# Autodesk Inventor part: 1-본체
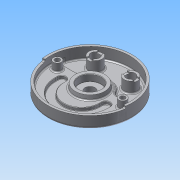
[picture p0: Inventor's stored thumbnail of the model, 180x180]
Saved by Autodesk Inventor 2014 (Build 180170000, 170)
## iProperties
Created: 2015-06
Part Number: 1-본체
Material: 알루미늄 6061
Document SubType Name: Modeling
Designer: Administrator
Density: 2.71 g/cm^3
Appearance: 알루미늄 - 평지
Mass: 1077.33 g
Surface Area: 1041.67 cm^2
Volume: 397.54 cm^3
Author: Administrator
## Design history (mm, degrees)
sketch "스케치1"
  geometry: C1 r 95 at (0, 0); 1 further point
  constraints: 1 centre point, 1 coincident
  dimensions: "d0" = 190 diameter of C1
extrude "돌출1" new body sketch "스케치1" distance "d1" = 32; taper "d2" = 0 deg
sketch "스케치2"
  geometry: C1 r 95 at (0, 0) reference; C2 r 90 at (0, 0)
  constraints: 1 centre point, 1 coincident
  dimensions: "d3" = 180 diameter of C2
extrude "돌출2" cut sketch "스케치2" distance "d4" = 18; taper "d5" = 0 deg
sketch "스케치3"
  geometry: L1 (-88.566, 16)-(88.566, 16); A1 r 90 centre (0, 0) between (-88.566, 16) and (88.566, 16) reference; A2 r 90 centre (0, 0) between (88.566, 16) and (-88.566, 16); A3 r 42 centre (0, 0) between (38.833, 16) and (-38.833, 16)
  constraints: 6 point on circle, 2 centre point, 2 end point, 2 point on line, 1 coincident, 1 concentric, 1 horizontal
  dimensions: "d6" = 16 distance from line of L1 A1.centre; "d7" = 84 diameter of A3
extrude "돌출3" cut sketch "스케치3" distance "d8" = 7; taper "d9" = 0 deg
sketch "스케치4"
  geometry: C1 r 35 at (0, 0); A1 r 42 centre (0, 0) between (38.833, 16) and (-38.833, 16) reference
  constraints: 1 centre point, 1 coincident
  dimensions: "d10" = 70 diameter of C1
extrude "돌출4" join sketch "스케치4" distance "d11" = 10; taper "d12" = -10 deg
sketch "스케치5"
  geometry: L1 (88.566, 16)-(38.833, 16) reference; L2 (-87.972, -19)-(87.972, -19); L3 (0, 0)-(0, -90); L4 (-88.904, -14)-(88.904, -14); L5 (-59, -19)-(-59, -14); L6 (-41, -19)-(-41, -14); L7 (41, -19)-(41, -14); L8 (59, -19)-(59, -14); C1 r 35 at (0, 0) reference; A1 r 90 centre (0, 0) between (-88.566, 16) and (88.566, 16) reference; A2 r 42 centre (0, 0) between (38.833, 16) and (-38.833, 16) reference; A3 r 41 centre (0, -19) between (-41, -19) and (41, -19); A4 r 59 centre (0, -19) between (-59, -19) and (59, -19); A5 r 9 centre (-50, -14) between (-41, -14) and (-59, -14); A6 r 9 centre (50, -14) between (59, -14) and (41, -14)
  constraints: 14 end point, 13 point on circle, 9 point on line, 8 tangent, 4 centre point, 4 perpendicular, 3 parallel, 1 coincident, 1 midpoint
  dimensions: "d13" = 19 distance from line of L2 C1.centre; "d16" = 5 distance between parallel lines of L4 L2; "d17" = 59 radius of A4; "d18" = 41 radius of A3
extrude "돌출5" cut sketch "스케치5" distance "d19" = 7; taper "d20" = 0 deg
sketch "스케치7"
  geometry: L1 (-95, 0)-(95, 0); L2 (-89.124, -12.526)-(-94.075, -13.221); L3 (89.124, -12.526)-(94.075, -13.221); C1 r 95 at (0, 0) reference; A1 r 90 centre (0, 0) between (-89.124, -12.526) and (89.124, -12.526); A2 r 95 centre (0, 0) between (-94.075, -13.221) and (94.075, -13.221); 2 further points
  constraints: 6 end point, 4 point on circle, 2 centre point, 2 coincident, 1 horizontal, 2 other
  dimensions: "d28" = 190 distance of L1.start L1.end; "d29" = 8 deg angle of L2 L1; "d30" = 8 deg angle of L3 L1; "d31" = 95 radius of A2; "d32" = 0 distance from line of point (0, 0) L3; "d33" = 0 distance from line of point (0, 0) L1; "d34" = 0 distance from line of point (0, 0) L2; "d35" = 13.22144 distance from line of L1.end L3
extrude "돌출6" cut sketch "스케치7" distance "d36" = 5; taper "d37" = 0 deg
sketch "스케치8"
  geometry: C1 r 95 at (0, 0) reference; C2 r 15 at (40, 52); C3 r 15 at (-40, 52)
  constraints: 2 centre point, 1 horizontal alignment
  dimensions: "d43" = 30 diameter of C3; "d44" = 30 diameter of C2; "d45" = 80 distance of C3.centre C2.centre; "d46" = 40 horizontal distance of C1.centre C2.centre; "d47" = 52 vertical distance of C1.centre C2.centre
extrude "돌출7" join sketch "스케치8" stored distance "d48" = 7; taper "d49" = 0 deg
sketch "스케치9"
  geometry: C1 r 15 at (0, 0) reference; C2 r 15 at (80, 0) reference; 3 further points
  constraints: 2 coincident
hole "구멍1" sketch "스케치9" at (0, 0), (80, 0) diameter "d50" = 20; stored, may be unused: countersink angle "d54" = 90 deg, drill point angle "d56" = 118 deg; dims "d51" = 6, "d52" = 4, "d53" = 2, "d55" = 8
sketch "스케치10"
  geometry: L1 (6, -19.376)-(-6, -19.376); L2 (-6, -19.376)-(-6, 19.376); L3 (-6, 19.376)-(6, 19.376); L4 (6, 19.376)-(6, -19.376); L5 (6, -19.376)-(-6, 19.376); L6 (-6, -19.376)-(6, 19.376); L7 (59.502, 6)-(100.498, 6); L8 (100.498, 6)-(100.498, -6); L9 (100.498, -6)-(59.502, -6); L10 (59.502, -6)-(59.502, 6); L11 (59.502, 6)-(100.498, -6); L12 (100.498, 6)-(59.502, -6); C1 r 15 at (0, 0) reference; C2 r 10 at (80, 0) reference; C3 r 15 at (80, 0) reference; 3 further points
  constraints: 24 end point, 5 midpoint, 4 parallel, 2 horizontal, 2 perpendicular, 1 coincident
  dimensions: "d57" = 12 distance of L2.end L3.end; "d58" = 12 distance of L9.end L7.start; "d59" = 38.75256 distance of L3.end L1.start; "d60" = 40.99632 distance of L8.end L9.end
extrude "돌출8" cut sketch "스케치10" distance "d61" = 3; taper "d62" = 0 deg
sketch "스케치13"
  geometry: C1 r 95 at (0, 0) reference; C2 r 26 at (0, 0)
  constraints: 1 centre point, 1 coincident
  dimensions: "d71" = 52 diameter of C2
extrude "돌출9" join sketch "스케치13" distance "d72" = 12; taper "d73" = -15 deg
sketch "스케치14"
  geometry: C1 r 33.237 at (0, 0) reference; 1 further point
  constraints: 1 coincident
hole "구멍3" sketch "스케치14" at (0, 0) diameter "d74" = 23; stored, may be unused: countersink angle "d78" = 90 deg, drill point angle "d80" = 118 deg; dims "d75" = 6, "d76" = 50, "d77" = 15, "d79" = 8
sketch "스케치16"
  geometry: L1 (88.566, 16)-(38.833, 16) reference; L2 (-90, 0)-(90, 0); C1 r 9 at (-74, 0); C2 r 9 at (74, 0); A1 r 90 centre (0, 0) between (-88.566, 16) and (88.566, 16) reference; A2 r 42 centre (0, 0) between (38.833, 16) and (-38.833, 16) reference; A3 r 74 centre (0, 0) between (-74, 0) and (74, 0)
  constraints: 4 point on circle, 3 centre point, 2 end point, 2 point on line, 1 coincident, 1 parallel
  dimensions: "d83" = 180 distance of L2.start L2.end; "d84" = 148 diameter of A3; "d85" = 18 diameter of C2; "d86" = 18 diameter of C1
extrude "돌출10" join sketch "스케치16" stored distance "d87" = 12; taper "d88" = 0 deg
sketch "스케치17"
  geometry: C1 r 9 at (-74, 0) reference; C2 r 9 at (74, 0) reference; 2 further points
  constraints: 2 coincident
hole "구멍4" sketch "스케치17" at (-74, 0), (74, 0) diameter "d89" = 11; stored, may be unused: countersink angle "d93" = 90 deg, drill point angle "d95" = 118 deg; dims "d90" = 6, "d91" = 18, "d92" = 11, "d94" = 8
fillet "모깎기1" dims "d96" = 10
fillet "모깎기2" dims "d97" = 3
fillet "모깎기3" dims "d98" = 3
fillet "모깎기4" dims "d99" = 3
fillet "모깎기5" dims "d100" = 3
fillet "모깎기6" dims "d101" = 3
chamfer "모따기1" distance "d102" = 1; stored, may be unused: second distance "d103" = 2, angle "d104" = 45 deg
fillet "모깎기7" dims "d105" = 0.3
fillet "모깎기8" dims "d106" = 1
chamfer "모따기2" distance "d107" = 1; stored, may be unused: second distance "d108" = 2, angle "d109" = 45 deg
sketch "스케치19"
  geometry: C1 r 95 at (0, 0) reference; C2 r 68 at (0, 0)
  constraints: 1 centre point, 1 coincident, 1 other
  dimensions: "d110" = 136 diameter of C2
feature "엠보싱1" sketch "스케치19" dims "d111" = 0.5, "d112" = 0
fillet "모깎기10" dims "d114" = 3
chamfer "모따기3" distance "d115" = 1; stored, may be unused: second distance "d116" = 2, angle "d117" = 45 deg
fillet "모깎기11" dims "d118" = 3
fillet "모깎기12" dims "d119" = 5
fillet "모깎기13" dims "d120" = 3
node "솔리드1"
node "투영된 루프1"
other parameters: "d14" = 59, "d15" = 41
